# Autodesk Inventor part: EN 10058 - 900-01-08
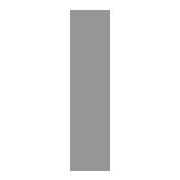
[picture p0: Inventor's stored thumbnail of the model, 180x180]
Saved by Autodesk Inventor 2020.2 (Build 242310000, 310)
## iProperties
Manager: www.cadconsulting.pl
Company: Fabian Stasiak CAD Consulting
Created: 2015-02
Part Number: EN 10058 - 900-01-08
Material: Steel, Mild
Description: Profile stalowe płaskie walcowane na gorąco do zastosowań ogólnych
Document SubType Name: Modeling
Standard: DIN EN 10058
Designer: F.Stasiak
Standard Revision: 2004
Standards Organization: DIN
Language: pl-PL
Size Designation: 60 x 10 - 870
Categories: <MemberInstance><Categories><Category DisplayName="Kształtowniki konstrukcyjne" InternalName="089c4875-fa83-4c05-b084-43b9cc11f5ed" Mnemonic="GRDR"><CategoryPar
Stock Number: 60 x 10
Density: 1 g/cm^3
Appearance: Semi-Polished
Catalog Web Link: www.expertbooks.pl
IsCustomPart: 1
G_L: 870,000 mm
Author: F.Stasiak
Subject: Zbiór ćwiczeń. Autodesk Inventor 2020. Kurs Professional
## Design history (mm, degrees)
node "Płaszczyzna początkowa"
node "Płaszczyzna końcowa"
sketch "Szkic"
  geometry: L1 (5, -30)-(-5, -30); L2 (-5, -30)-(-5, 30); L3 (-5, 30)-(5, 30); L4 (5, 30)-(5, -30); L5 (-6, 0)-(8, 0); L6 (0, -30)-(0, 40); L7 (0, 54)-(0, -44) reference; L8 (-9.2, 0)-(13.2, 0) reference
  constraints: 12 end point, 2 collinear, 2 parallel, 1 horizontal, 1 perpendicular
  dimensions: "d0" = 60 distance between parallel lines of L3 L1 (= G_W); "d1" = 10 distance between parallel lines of L4 L2 (= G_H); "d4" = 5 distance between parallel lines of L6 L4 (= 0.5 x d1); "d5" = 30 distance between parallel lines of L5 L3 (= 0.5 x d0)
extrude "Bryła" new body sketch "Szkic" stored distance "d2" = 870 (= G_L); taper "d3" = 0 deg
node "Driven Length"
  sketch "Sketch3"
    geometry: L1 (0, 0)-(10, 0) reference
    constraints: 2 end point, 1 horizontal
  workplane "Work Plane3"
  sketch "Sketch4"
    geometry: L1 (-2, 0)-(12, 0) reference; L2 (-2, 870)-(12, 870) reference
    dimensions: "d9" = 870 distance between parallel lines of L1 L2 (derived)
body "Solid1"
other parameters: "G_W" = 60 [user parameter; used in 1 equation term], "G_H" = 10 [user parameter; used in 1 equation term], "G_L" = 870 (= d9) [user parameter; used in 1 equation term], "G_OFFSET_START" = 0 [user parameter; used in 1 equation term], "G_OFFSET_END" = 0 [user parameter; used in 1 equation term], "d6" = 0 (computed from G_OFFSET_START), "d8" = 90 deg, "MAS" = 0.471 [user parameter]
